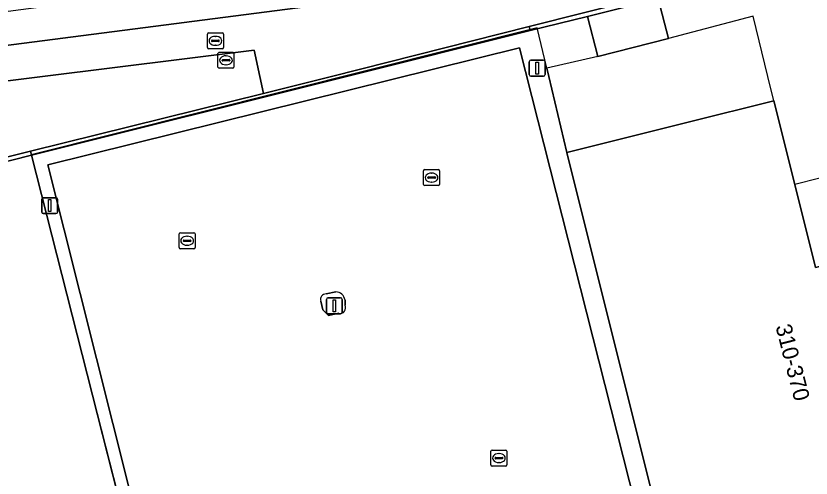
# Model space of a CAD drawing. Extents: x 160806 to 161707, y 383696 to 384148.
# Drawn here: x 160906.51 to 160956.33, y 383724.83 to 383753.81 of the extents above; entities that cross this region are included whole.
import ezdxf

# ---------------------------------------------------------------- set-up
doc = ezdxf.new("R2010")
doc.units = 0
for name, color, linetype in [('IMGEO_Brandkraan', 7, 'Continuous'), ('IMGEO_Dek', 7, 'Continuous'), ('IMGEO_Fietspad_open', 7, 'Continuous'), ('IMGEO_Groenvoorziening', 7, 'Continuous'), ('IMGEO_Lichtmast', 7, 'Continuous'), ('IMGEO_Muur', 7, 'Continuous'), ('IMGEO_Pand', 7, 'Continuous'), ('IMGEO_Pand_nummerreeks', 7, 'Continuous'), ('IMGEO_Pand_overbouw', 7, 'Continuous'), ('IMGEO_Parkeervlak_gesloten', 7, 'Continuous'), ('IMGEO_Parkeervlak_open', 7, 'Continuous'), ('IMGEO_Rioolput', 7, 'Continuous'), ('IMGEO_Verkeerseiland_gesloten', 7, 'Continuous'), ('IMGEO_Voetpad_gesloten', 7, 'Continuous'), ('IMGEO_Voetpad_open', 7, 'Continuous')]:
    doc.layers.add(name, color=color, linetype=linetype)

msp = doc.modelspace()

# ---------------------------------------------------------------- linework, layer by layer
at = {"layer": 'IMGEO_Brandkraan'}
for p, q in [((160919.175, 383750.595), (160919.175, 383751.447)), ((160919.25, 383751.521), (160920.102, 383751.521)), ((160920.176, 383751.447), (160920.176, 383750.595)), ((160919.434, 383751.015), (160919.434, 383751.027)), ((160919.872, 383750.978), (160919.474, 383750.978)), ((160919.477, 383751.064), (160919.875, 383751.064)), ((160919.663, 383751.301), (160919.688, 383751.301)), ((160919.918, 383751.027), (160919.918, 383751.015)), ((160920.102, 383750.521), (160919.25, 383750.521)), ((160919.686, 383750.741), (160919.661, 383750.741))]:
    msp.add_line(p, q, dxfattribs=at)
for points in [[(160919.175, 383750.595), (160919.175, 383751.447)], [(160919.25, 383751.521), (160920.102, 383751.521)], [(160920.176, 383751.447), (160920.176, 383750.595)], [(160920.102, 383750.521), (160919.25, 383750.521)]]:
    msp.add_lwpolyline(points, dxfattribs=at)
for centre, radius, start, end in [((160919.252, 383751.445), 0.0765, 91.552, 178.448), ((160919.252, 383751.445), 0.0765, 91.552, 178.448), ((160920.1, 383751.445), 0.0765, 1.552, 88.448), ((160920.1, 383751.445), 0.0765, 1.552, 88.448), ((160919.474, 383751.024), 0.0403, 85.8775, 175.7526), ((160919.471, 383751.014), 0.0366, 178.938, 274.7102), ((160919.875, 383751.021), 0.043, 264.8664, 352.4533), ((160919.879, 383751.026), 0.0386, 1.7309, 96.639), ((160919.252, 383750.597), 0.0765, 181.552, 268.448), ((160919.252, 383750.597), 0.0765, 181.552, 268.448), ((160920.1, 383750.597), 0.0765, 271.552, 358.448), ((160920.1, 383750.597), 0.0765, 271.552, 358.448)]:
    msp.add_arc(centre, radius, start, end, dxfattribs=at)
for centre, major_axis, ratio, start_param, end_param in [((160919.662, 383751.021), (-0.387, 0.002), 0.722429, 4.712389, 7.853982), ((160919.687, 383751.021), (-0.39, 0.002), 0.717154, 1.570796, 4.712389)]:
    msp.add_ellipse(centre, major_axis=major_axis, ratio=ratio, start_param=start_param, end_param=end_param, dxfattribs=at)
at = {"layer": 'IMGEO_Dek'}
msp.add_lwpolyline([(160965.894, 383710.159), (160949.913, 383709.678), (160949.497, 383711.315), (160949.382, 383711.774), (160941.019, 383745.231), (160939.898, 383750), (160939.772, 383750.534), (160939.177, 383753.065), (160907.479, 383745.104), (160918.048, 383703.574), (160983.268, 383705.804)], dxfattribs=at)
at = {"layer": 'IMGEO_Fietspad_open'}
msp.add_lwpolyline([(160926.307, 383756.75), (160894.194, 383752.541), (160893.833, 383752.495), (160894.094, 383750.419), (160894.884, 383750.529), (160931.609, 383755.303)], dxfattribs=at)
at = {"layer": 'IMGEO_Groenvoorziening'}
for points in [[(160907.436, 383745.322), (160922.028, 383748.942), (160921.796, 383750), (160921.433, 383751.653), (160908.189, 383750), (160895.153, 383748.373), (160895.894, 383742.401), (160900.906, 383743.686)], [(160907.502, 383745.064), (160901.057, 383743.443), (160900.906, 383743.686), (160895.894, 383742.401), (160911.759, 383711.533), (160915.971, 383703.725), (160917.974, 383703.804)]]:
    msp.add_lwpolyline(points, close=True, dxfattribs=at)
at = {"layer": 'IMGEO_Lichtmast'}
for p, q in [((160938.675, 383750.128), (160938.675, 383750.928)), ((160938.675, 383750.928), (160938.675, 383750.128)), ((160938.775, 383751.028), (160939.565, 383751.028)), ((160939.565, 383751.028), (160938.775, 383751.028)), ((160939.665, 383750.928), (160939.665, 383750.128)), ((160939.665, 383750.128), (160939.665, 383750.928)), ((160939.565, 383750.028), (160938.775, 383750.028)), ((160938.775, 383750.028), (160939.565, 383750.028)), ((160908.133, 383741.509), (160908.133, 383742.309)), ((160908.133, 383742.309), (160908.133, 383741.509)), ((160908.233, 383742.409), (160909.023, 383742.409)), ((160909.023, 383742.409), (160908.233, 383742.409)), ((160909.123, 383742.309), (160909.123, 383741.509)), ((160909.123, 383741.509), (160909.123, 383742.309)), ((160909.023, 383741.409), (160908.233, 383741.409)), ((160908.233, 383741.409), (160909.023, 383741.409)), ((160925.963, 383735.231), (160925.963, 383736.031)), ((160925.963, 383736.031), (160925.963, 383735.231)), ((160926.063, 383736.131), (160926.853, 383736.131)), ((160926.853, 383736.131), (160926.063, 383736.131)), ((160926.953, 383736.031), (160926.953, 383735.231)), ((160926.953, 383735.231), (160926.953, 383736.031)), ((160926.853, 383735.131), (160926.063, 383735.131)), ((160926.063, 383735.131), (160926.853, 383735.131))]:
    msp.add_line(p, q, dxfattribs=at)
for points in [[(160939.095, 383750.903), (160939.245, 383750.903), (160939.245, 383750.153), (160939.095, 383750.153), (160939.095, 383750.903)], [(160908.553, 383742.284), (160908.703, 383742.284), (160908.703, 383741.534), (160908.553, 383741.534), (160908.553, 383742.284)], [(160926.383, 383736.006), (160926.533, 383736.006), (160926.533, 383735.256), (160926.383, 383735.256), (160926.383, 383736.006)]]:
    msp.add_lwpolyline(points, dxfattribs=at)
for centre, start, end in [((160938.775, 383750.928), 90, 180), ((160938.775, 383750.928), 90, 180), ((160939.565, 383750.928), 0, 90), ((160939.565, 383750.928), 360, 90), ((160938.775, 383750.128), 180, 270), ((160938.775, 383750.128), 180, 270), ((160939.565, 383750.128), 270, 0), ((160939.565, 383750.128), 270, 0), ((160908.233, 383742.309), 90, 180), ((160908.233, 383742.309), 90, 180), ((160909.023, 383742.309), 0, 90), ((160909.023, 383742.309), 360, 90), ((160908.233, 383741.509), 180, 270), ((160908.233, 383741.509), 180, 270), ((160909.023, 383741.509), 270, 0), ((160909.023, 383741.509), 270, 0), ((160926.063, 383736.031), 90, 180), ((160926.063, 383736.031), 90, 180), ((160926.853, 383736.031), 0, 90), ((160926.853, 383736.031), 360, 90), ((160926.063, 383735.231), 180, 270), ((160926.063, 383735.231), 180, 270), ((160926.853, 383735.231), 270, 0), ((160926.853, 383735.231), 270, 0)]:
    msp.add_arc(centre, 0.1, start, end, dxfattribs=at)
at = {"layer": 'IMGEO_Muur'}
for points in [[(160959.333, 383758.368), (160938.676, 383753.139), (160938.74, 383752.883), (160942.334, 383753.775), (160946.757, 383754.904), (160959.395, 383758.125)], [(160907.436, 383745.322), (160907.502, 383745.064), (160927.222, 383750), (160938.74, 383752.883), (160938.676, 383753.139), (160926.276, 383750), (160922.028, 383748.942)], [(160907.502, 383745.064), (160907.436, 383745.322), (160900.906, 383743.686), (160901.057, 383743.443)]]:
    msp.add_lwpolyline(points, close=True, dxfattribs=at)
at = {"layer": 'IMGEO_Pand'}
for points in [[(160946.757, 383754.904), (160942.334, 383753.775), (160942.978, 383751.256), (160947.4, 383752.385)], [(160958.607, 383730.26), (160963.657, 383731.523), (160962.631, 383735.625), (160961.795, 383738.969), (160961.709, 383739.314), (160956.607, 383738.039), (160955.357, 383743.043), (160955.308, 383743.237), (160953.999, 383748.475), (160948.634, 383747.134), (160944.207, 383746.028), (160941.019, 383745.231), (160949.382, 383711.774), (160949.497, 383711.315), (160955.552, 383712.828), (160956.184, 383710.298), (160960.518, 383711.382), (160959.898, 383713.862), (160962.541, 383714.522)]]:
    msp.add_lwpolyline(points, close=True, dxfattribs=at)
at = {"layer": 'IMGEO_Pand_overbouw'}
for points in [[(160942.978, 383751.256), (160939.772, 383750.534), (160939.898, 383750), (160941.019, 383745.231), (160944.207, 383746.028), (160948.634, 383747.134), (160953.999, 383748.475), (160953.626, 383750), (160952.702, 383753.779), (160947.4, 383752.385)], [(160962.624, 383741.824), (160961.54, 383741.548), (160961.142, 383742.274), (160960.626, 383742.816), (160960.1, 383743.212), (160959.552, 383743.495), (160958.926, 383743.665), (160958.73, 383743.717), (160958.447, 383743.791), (160957.901, 383743.793), (160957.479, 383743.751), (160956.788, 383743.617), (160955.308, 383743.237), (160956.607, 383738.039), (160961.709, 383739.314), (160962.561, 383735.906), (160964.085, 383736.287)]]:
    msp.add_lwpolyline(points, close=True, dxfattribs=at)
at = {"layer": 'IMGEO_Parkeervlak_gesloten'}
for points in [[(160943.296, 383711.315), (160947.996, 383712.552), (160938.057, 383751.803), (160908.505, 383744.478), (160918.679, 383703.958), (160945.346, 383704.857)], [(160925.949, 383736.372), (160926.557, 383736.503)], [(160927.132, 383735.986), (160927.134, 383735.668)], [(160926.097, 383735.014), (160925.739, 383735.38), (160925.622, 383735.913)], [(160926.744, 383735.158), (160926.097, 383735.014)]]:
    msp.add_lwpolyline(points, dxfattribs=at)
for centre, radius, start, end in [((160926.547, 383735.913), 0.59, 7.0647, 89.016), ((160925.923, 383736.045), 0.328, 85.3696, 203.6969), ((160926.817, 383735.506), 0.356, 258.0785, 27.1108)]:
    msp.add_arc(centre, radius, start, end, dxfattribs=at)
at = {"layer": 'IMGEO_Parkeervlak_open'}
msp.add_lwpolyline([(160959.395, 383758.125), (160946.757, 383754.904), (160947.4, 383752.385), (160942.978, 383751.256), (160942.334, 383753.775), (160938.74, 383752.883), (160927.222, 383750), (160907.502, 383745.064), (160917.974, 383703.804), (160918.795, 383703.836), (160945.341, 383704.883), (160945.396, 383704.652), (160983.265, 383705.961)], dxfattribs=at)
msp.add_lwpolyline([(160955.357, 383743.043), (160956.607, 383738.039), (160961.709, 383739.314), (160961.795, 383738.969), (160962.631, 383735.625), (160963.657, 383731.523), (160958.607, 383730.26), (160962.541, 383714.522), (160959.898, 383713.862), (160960.518, 383711.382), (160956.184, 383710.298), (160955.552, 383712.828), (160949.497, 383711.315), (160949.382, 383711.774), (160941.019, 383745.231), (160944.207, 383746.028), (160948.634, 383747.134), (160953.999, 383748.475), (160955.308, 383743.237)], close=True, dxfattribs=at)
at = {"layer": 'IMGEO_Rioolput'}
for p, q in [((160918.515, 383751.816), (160918.515, 383752.668)), ((160918.59, 383752.742), (160919.442, 383752.742)), ((160919.003, 383752.522), (160919.028, 383752.522)), ((160919.516, 383752.668), (160919.516, 383751.816)), ((160918.774, 383752.236), (160918.774, 383752.248)), ((160919.212, 383752.199), (160918.814, 383752.199)), ((160918.817, 383752.285), (160919.215, 383752.285)), ((160919.026, 383751.962), (160919.001, 383751.962)), ((160919.258, 383752.248), (160919.258, 383752.236)), ((160919.442, 383751.742), (160918.59, 383751.742)), ((160932.055, 383743.242), (160932.055, 383744.094)), ((160932.13, 383744.168), (160932.982, 383744.168)), ((160932.543, 383743.948), (160932.568, 383743.948)), ((160933.056, 383744.094), (160933.056, 383743.242)), ((160932.314, 383743.662), (160932.314, 383743.674)), ((160932.752, 383743.625), (160932.354, 383743.625)), ((160932.357, 383743.711), (160932.755, 383743.711)), ((160932.798, 383743.674), (160932.798, 383743.662)), ((160932.982, 383743.168), (160932.13, 383743.168)), ((160932.566, 383743.388), (160932.541, 383743.388)), ((160916.743, 383739.28), (160916.743, 383740.132)), ((160916.818, 383740.206), (160917.67, 383740.206)), ((160917.231, 383739.986), (160917.256, 383739.986)), ((160917.744, 383740.132), (160917.744, 383739.28)), ((160917.002, 383739.7), (160917.002, 383739.712)), ((160917.44, 383739.663), (160917.042, 383739.663)), ((160917.045, 383739.749), (160917.443, 383739.749)), ((160917.486, 383739.712), (160917.486, 383739.7)), ((160917.67, 383739.206), (160916.818, 383739.206)), ((160917.254, 383739.426), (160917.229, 383739.426)), ((160936.274, 383725.657), (160936.274, 383726.509)), ((160936.349, 383726.583), (160937.201, 383726.583)), ((160937.275, 383726.509), (160937.275, 383725.657)), ((160936.533, 383726.077), (160936.533, 383726.089)), ((160936.971, 383726.04), (160936.573, 383726.04)), ((160936.576, 383726.126), (160936.974, 383726.126)), ((160936.762, 383726.363), (160936.787, 383726.363)), ((160937.017, 383726.089), (160937.017, 383726.077)), ((160937.201, 383725.583), (160936.349, 383725.583)), ((160936.785, 383725.803), (160936.76, 383725.803))]:
    msp.add_line(p, q, dxfattribs=at)
for points in [[(160918.515, 383751.816), (160918.515, 383752.668)], [(160918.59, 383752.742), (160919.442, 383752.742)], [(160919.516, 383752.668), (160919.516, 383751.816)], [(160919.442, 383751.742), (160918.59, 383751.742)], [(160932.055, 383743.242), (160932.055, 383744.094)], [(160932.13, 383744.168), (160932.982, 383744.168)], [(160933.056, 383744.094), (160933.056, 383743.242)], [(160932.982, 383743.168), (160932.13, 383743.168)], [(160916.743, 383739.28), (160916.743, 383740.132)], [(160916.818, 383740.206), (160917.67, 383740.206)], [(160917.744, 383740.132), (160917.744, 383739.28)], [(160917.67, 383739.206), (160916.818, 383739.206)], [(160936.274, 383725.657), (160936.274, 383726.509)], [(160936.349, 383726.583), (160937.201, 383726.583)], [(160937.275, 383726.509), (160937.275, 383725.657)], [(160937.201, 383725.583), (160936.349, 383725.583)]]:
    msp.add_lwpolyline(points, dxfattribs=at)
for centre, radius, start, end in [((160918.592, 383752.666), 0.0765, 91.552, 178.448), ((160918.592, 383752.666), 0.0765, 91.552, 178.448), ((160919.44, 383752.666), 0.0765, 1.552, 88.448), ((160919.44, 383752.666), 0.0765, 1.552, 88.448), ((160918.814, 383752.245), 0.0403, 85.8775, 175.7526), ((160918.811, 383752.235), 0.0366, 178.938, 274.7102), ((160919.215, 383752.242), 0.043, 264.8664, 352.4533), ((160919.219, 383752.247), 0.0386, 1.7309, 96.639), ((160918.592, 383751.818), 0.0765, 181.552, 268.448), ((160918.592, 383751.818), 0.0765, 181.552, 268.448), ((160919.44, 383751.818), 0.0765, 271.552, 358.448), ((160919.44, 383751.818), 0.0765, 271.552, 358.448), ((160932.132, 383744.092), 0.0765, 91.552, 178.448), ((160932.132, 383744.092), 0.0765, 91.552, 178.448), ((160932.98, 383744.092), 0.0765, 1.552, 88.448), ((160932.98, 383744.092), 0.0765, 1.552, 88.448), ((160932.354, 383743.671), 0.0403, 85.8775, 175.7526), ((160932.351, 383743.661), 0.0366, 178.938, 274.7102), ((160932.755, 383743.668), 0.043, 264.8664, 352.4533), ((160932.759, 383743.673), 0.0386, 1.7309, 96.639), ((160932.132, 383743.244), 0.0765, 181.552, 268.448), ((160932.132, 383743.244), 0.0765, 181.552, 268.448), ((160932.98, 383743.244), 0.0765, 271.552, 358.448), ((160932.98, 383743.244), 0.0765, 271.552, 358.448), ((160916.82, 383740.13), 0.0765, 91.552, 178.448), ((160916.82, 383740.13), 0.0765, 91.552, 178.448), ((160917.668, 383740.13), 0.0765, 1.552, 88.448), ((160917.668, 383740.13), 0.0765, 1.552, 88.448), ((160917.042, 383739.709), 0.0403, 85.8775, 175.7526), ((160917.039, 383739.699), 0.0366, 178.938, 274.7102), ((160917.443, 383739.706), 0.043, 264.8664, 352.4533), ((160917.447, 383739.711), 0.0386, 1.7309, 96.639), ((160916.82, 383739.282), 0.0765, 181.552, 268.448), ((160916.82, 383739.282), 0.0765, 181.552, 268.448), ((160917.668, 383739.282), 0.0765, 271.552, 358.448), ((160917.668, 383739.282), 0.0765, 271.552, 358.448), ((160936.351, 383726.507), 0.0765, 91.552, 178.448), ((160936.351, 383726.507), 0.0765, 91.552, 178.448), ((160937.199, 383726.507), 0.0765, 1.552, 88.448), ((160937.199, 383726.507), 0.0765, 1.552, 88.448), ((160936.573, 383726.086), 0.0403, 85.8775, 175.7526), ((160936.57, 383726.076), 0.0366, 178.938, 274.7102), ((160936.974, 383726.083), 0.043, 264.8664, 352.4533), ((160936.978, 383726.088), 0.0386, 1.7309, 96.639), ((160936.351, 383725.659), 0.0765, 181.552, 268.448), ((160936.351, 383725.659), 0.0765, 181.552, 268.448), ((160937.199, 383725.659), 0.0765, 271.552, 358.448), ((160937.199, 383725.659), 0.0765, 271.552, 358.448)]:
    msp.add_arc(centre, radius, start, end, dxfattribs=at)
for centre, major_axis, ratio, start_param, end_param in [((160919.002, 383752.242), (-0.387, 0.002), 0.722429, 4.712389, 7.853982), ((160919.027, 383752.242), (-0.39, 0.002), 0.717154, 1.570796, 4.712389), ((160932.542, 383743.668), (-0.387, 0.002), 0.722429, 4.712389, 7.853982), ((160932.567, 383743.668), (-0.39, 0.002), 0.717154, 1.570796, 4.712389), ((160917.23, 383739.706), (-0.387, 0.002), 0.722429, 4.712389, 7.853982), ((160917.255, 383739.706), (-0.39, 0.002), 0.717154, 1.570796, 4.712389), ((160936.761, 383726.083), (-0.387, 0.002), 0.722429, 4.712389, 7.853982), ((160936.786, 383726.083), (-0.39, 0.002), 0.717154, 1.570796, 4.712389)]:
    msp.add_ellipse(centre, major_axis=major_axis, ratio=ratio, start_param=start_param, end_param=end_param, dxfattribs=at)
at = {"layer": 'IMGEO_Verkeerseiland_gesloten'}
for points in [[(160926.557, 383736.503), (160925.949, 383736.372)], [(160927.134, 383735.668), (160927.132, 383735.986)], [(160925.622, 383735.913), (160925.739, 383735.38), (160926.097, 383735.014), (160926.744, 383735.158)]]:
    msp.add_lwpolyline(points, dxfattribs=at)
for centre, radius, start, end in [((160926.547, 383735.913), 0.59, 7.0647, 89.016), ((160925.923, 383736.045), 0.328, 85.3696, 203.6969), ((160926.817, 383735.506), 0.356, 258.0785, 27.1108)]:
    msp.add_arc(centre, radius, start, end, dxfattribs=at)
at = {"layer": 'IMGEO_Voetpad_gesloten'}
for points in [[(160965.894, 383710.159), (160949.913, 383709.678), (160949.497, 383711.315), (160949.382, 383711.774), (160941.019, 383745.231), (160939.898, 383750), (160939.772, 383750.534), (160939.177, 383753.065), (160907.479, 383745.104), (160918.048, 383703.574), (160983.268, 383705.804)], [(160983.262, 383706.136), (160945.346, 383704.857), (160918.679, 383703.958), (160908.505, 383744.478), (160938.057, 383751.803), (160947.996, 383712.552), (160943.296, 383711.315)]]:
    msp.add_lwpolyline(points, dxfattribs=at)
at = {"layer": 'IMGEO_Voetpad_open'}
msp.add_lwpolyline([(160931.609, 383755.303), (160894.884, 383750.529), (160894.95, 383750), (160895.153, 383748.373), (160908.189, 383750), (160921.433, 383751.653), (160921.796, 383750), (160922.028, 383748.942), (160926.276, 383750), (160938.676, 383753.139), (160959.333, 383758.368), (160960.762, 383758.727), (160971.208, 383761.353)], dxfattribs=at)

# ---------------------------------------------------------------- texts
at = {"layer": 'IMGEO_Pand_nummerreeks'}
msp.add_text('310-370', height=1, rotation=284.2034, dxfattribs=at).set_placement((160954.098, 383734.342))

doc.saveas('drawing.dxf')
